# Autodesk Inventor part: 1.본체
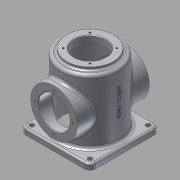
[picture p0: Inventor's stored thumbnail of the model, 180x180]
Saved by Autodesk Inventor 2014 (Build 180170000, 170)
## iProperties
Created: 2015-10
Part Number: 1.본체
Material: 알루미늄 6061
Document SubType Name: Modeling
Designer: Owner
Density: 2.71 g/cm^3
Appearance: 알루미늄 - 평지
Mass: 993.404 g
Surface Area: 1041.56 cm^2
Volume: 366.57 cm^3
Author: Owner
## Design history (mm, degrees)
sketch "스케치1"
  geometry: C1 r 50 at (0, 0); 1 further point
  constraints: 1 centre point, 1 coincident
  dimensions: "d0" = 100 diameter of C1
extrude "돌출1" new body sketch "스케치1" distance "d1" = 60; taper "d3" = 0 deg; dims "d2" = 60, "d4" = 0
sketch "스케치2"
  geometry: C1 r 50 at (0, 0) reference; C2 r 40 at (0, 0)
  constraints: 1 centre point, 1 coincident
  dimensions: "d5" = 80 diameter of C2
extrude "돌출2" join sketch "스케치2" distance "d6" = 5; taper "d7" = 0 deg
hole "구멍1" diameter "d10" = 54; stored, may be unused: countersink angle "d14" = 90 deg, drill point angle "d16" = 118 deg; dims "d11" = 6, "d12" = 90, "d13" = 112, "d15" = 8, "d19" = 10, "d20" = 10
sketch "스케치3"
  geometry: L1 (60, -60)-(-60, -60); L2 (-60, -60)-(-60, 60); L3 (-60, 60)-(60, 60); L4 (60, 60)-(60, -60); L5 (60, -60)-(-60, 60); L6 (-60, -60)-(60, 60); C1 r 50 at (0, 0) reference
  constraints: 12 end point, 2 midpoint, 2 parallel, 1 horizontal, 1 perpendicular
  dimensions: "d17" = 120 distance of L2.end L3.end; "d18" = 120 distance of L1.end L2.end
extrude "돌출3" join sketch "스케치3" distance "d21" = 10; taper "d22" = 0 deg
sketch "스케치4"
  geometry: L1 (-60, -60)-(60, -60) reference; L2 (-60, 60)-(-60, -60) reference; C1 r 4 at (-50, -50)
  constraints: 1 centre point
  dimensions: "d23" = 8 diameter of C1; "d24" = 10 distance from line of L1 C1.centre; "d25" = 10 distance from line of C1.centre L2
extrude "돌출4" cut sketch "스케치4" stored distance "d26" = 10; taper "d27" = 0 deg
sketch "스케치5"
  geometry: L1 (-22.981, 22.981)-(0, 0); L2 (0, 0)-(-32.5, 0); C1 r 40 at (0, 0) reference
  constraints: 4 end point, 1 equal length, 1 horizontal
  dimensions: "d34" = 32.5 distance of L1.end L2.end; "d35" = 45 deg angle of L2 L1
hole "구멍2" sketch "스케치5" at (-22.981, 22.981) diameter "d36" = 3.242; stored, may be unused: countersink angle "d40" = 90 deg, drill point angle "d42" = 118 deg; dims "d37" = 8, "d38" = 90, "d39" = 112, "d41" = 10
node "작업 평면1"
sketch "스케치6"
  geometry: C1 r 40 at (0, 0); 1 further point
  constraints: 1 centre point, 1 coincident
  dimensions: "d47" = 80 diameter of C1
extrude "돌출5" join sketch "스케치6" stored distance "d48" = 10; taper "d49" = 0 deg
hole "구멍3" diameter "d52" = 54; stored, may be unused: countersink angle "d56" = 90 deg, drill point angle "d58" = 118 deg; dims "d50" = 10, "d51" = 10, "d53" = 8, "d54" = 90, "d55" = 112, "d57" = 10
sketch "스케치7"
  geometry: C1 r 27 at (0, 0) reference; 1 further point
  constraints: 1 vertical alignment
  dimensions: "d59" = 32.5 distance of C1.centre point (0, 32.5)
hole "구멍4" sketch "스케치7" at (0, 32.5) diameter "d60" = 3.242; stored, may be unused: countersink angle "d64" = 90 deg, drill point angle "d66" = 118 deg; dims "d61" = 8, "d62" = 90, "d63" = 112, "d65" = 10
chamfer "모따기1" distance "d70" = 3; stored, may be unused: second distance "d71" = 2, angle "d72" = 45 deg
chamfer "모따기2" distance "d73" = 1; stored, may be unused: second distance "d74" = 2, angle "d75" = 45 deg
fillet "모깎기1" dims "d76" = 10
fillet "모깎기2" dims "d77" = 5
fillet "모깎기3" dims "d78" = 3
node "작업 평면2"
sketch "스케치8"
  geometry: L1 (-50, -60)-(50, -60) reference; 2 further points
  constraints: 1 vertical alignment, 1 other
  dimensions: "d80" = 70 distance from line of L1 point (0, 10)
feature "엠보싱2" sketch "스케치8" dims "d1" = 60, "d2" = 60, "d3" = 0, "d4" = 0, "d17" = 120, "d18" = 120, "d83" = 0.5, "d84" = 0
node "솔리드1"
pattern_linear "직사각형 패턴1" dims "d30" = 100
pattern_circular "원형 패턴1" dims angle "d44" = 360 deg
pattern_circular "원형 패턴2" dims angle "d68" = 360 deg
mirror "대칭1"
other parameters: "d46" = 62
